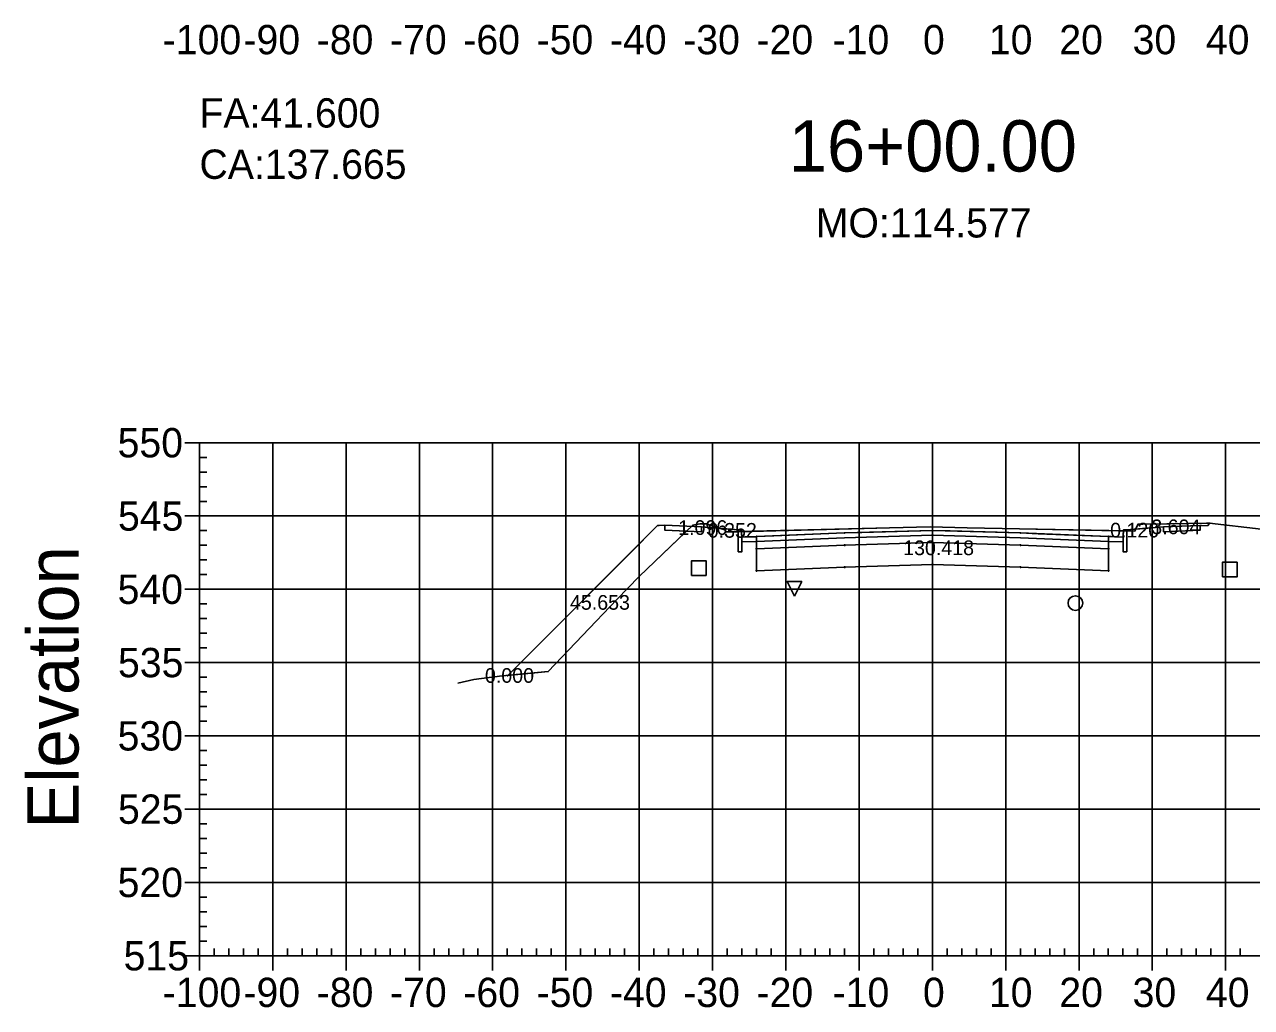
# Model space of a CAD drawing. Extents: x 704834 to 709892, y 372981 to 377533.
# Drawn here: x 704913 to 705080.4, y 373285.8 to 373419.9 of the extents above; entities that cross this region are included whole.
import ezdxf

# ---------------------------------------------------------------- set-up
doc = ezdxf.new("R2010")
doc.units = 0
for name, color, linetype in [('1', 7, 'Continuous'), ('10', 7, 'Continuous'), ('13', 7, 'Continuous'), ('14', 7, 'Continuous'), ('4', 7, 'Continuous'), ('57', 7, 'Continuous'), ('59', 7, 'Continuous'), ('60', 7, 'Continuous'), ('Default_Xsect', 7, 'Continuous'), ('Existing', 7, 'Continuous')]:
    doc.layers.add(name, color=color, linetype=linetype)

msp = doc.modelspace()

# ---------------------------------------------------------------- linework, layer by layer
for points in [[(704999.38, 373351.51), (704978.9, 373331.03)], [(705000.38, 373351.55), (704999.38, 373351.51)], [(705010.38, 373350.95), (705005.38, 373351.35)], [(705063.38, 373350.94), (705068.38, 373351.34)], [(705073.38, 373351.54), (705074.38, 373351.5)], [(705074.38, 373351.5), (705074.7, 373351.82)]]:
    msp.add_lwpolyline(points)
for points in [[(705005.38, 373351.35), (705000.38, 373351.55), (705000.38, 373350.88), (705005.38, 373350.68)], [(705010.88, 373349.95), (705010.79, 373350.95), (705010.38, 373350.95), (705010.38, 373347.95), (705010.88, 373347.95)], [(705036.88, 373350.2), (705048.88, 373349.84), (705060.88, 373349.36), (705060.88, 373350.02), (705048.88, 373350.5), (705036.88, 373350.86), (705024.88, 373350.51), (705012.88, 373350.03), (705012.88, 373349.36), (705024.88, 373349.84)], [(705062.88, 373347.94), (705063.38, 373347.94), (705063.38, 373350.94), (705062.96, 373350.94), (705062.88, 373349.94)], [(705068.38, 373350.67), (705073.38, 373350.87), (705073.38, 373351.54), (705068.38, 373351.34)], [(705012.88, 373350.03), (705010.88, 373349.95), (705010.88, 373349.28), (705012.88, 373349.36)], [(705036.88, 373349.2), (705048.88, 373348.84), (705060.88, 373348.36), (705060.88, 373349.36), (705048.88, 373349.84), (705036.88, 373350.2), (705024.88, 373349.84), (705012.88, 373349.36), (705012.88, 373348.36), (705024.88, 373348.84)], [(705036.88, 373346.2), (705048.88, 373345.84), (705060.88, 373345.36), (705060.88, 373348.36), (705048.88, 373348.84), (705036.88, 373349.2), (705024.88, 373348.84), (705012.88, 373348.36), (705012.88, 373345.36), (705024.88, 373345.84)], [(705024.83, 373348.79), (705024.93, 373348.79), (705024.93, 373348.89), (705024.83, 373348.89)], [(705036.83, 373350.15), (705036.93, 373350.15), (705036.93, 373350.25), (705036.83, 373350.25)], [(705036.83, 373349.15), (705036.93, 373349.15), (705036.93, 373349.25), (705036.83, 373349.25)], [(705048.83, 373348.79), (705048.93, 373348.79), (705048.93, 373348.89), (705048.83, 373348.89)], [(705060.88, 373349.36), (705062.88, 373349.28), (705062.88, 373349.94), (705060.88, 373350.02)], [(705012.83, 373348.31), (705012.93, 373348.31), (705012.93, 373348.41), (705012.83, 373348.41)], [(705060.83, 373348.31), (705060.93, 373348.31), (705060.93, 373348.41), (705060.83, 373348.41)], [(705012.83, 373345.31), (705012.93, 373345.31), (705012.93, 373345.41), (705012.83, 373345.41)], [(705024.83, 373345.79), (705024.93, 373345.79), (705024.93, 373345.89), (705024.83, 373345.89)], [(705036.83, 373346.15), (705036.93, 373346.15), (705036.93, 373346.25), (705036.83, 373346.25)], [(705048.83, 373345.79), (705048.93, 373345.79), (705048.93, 373345.89), (705048.83, 373345.89)], [(705060.83, 373345.31), (705060.93, 373345.31), (705060.93, 373345.41), (705060.83, 373345.41)]]:
    msp.add_lwpolyline(points, close=True)
at = {"layer": '1'}
for points in [[(704978.94, 373331.07), (704984.45, 373331.6), (704993.8, 373341.43), (704996.86, 373344.58), (705003.32, 373350.76), (705000.38, 373350.88), (705000.38, 373351.55), (704999.57, 373351.52), (704999.38, 373351.51)], [(705003.32, 373350.76), (705004.17, 373351.58), (705005.13, 373351.73), (705006, 373351.74), (705007.82, 373351.15), (705006.35, 373351.27), (705005.38, 373351.35), (705005.38, 373350.68)], [(705007.82, 373351.15), (705008.54, 373350.92), (705008.68, 373350.64), (705010.38, 373350.68), (705010.38, 373350.95)], [(705010.38, 373350.68), (705031.01, 373351.2), (705036.55, 373351.34), (705041.59, 373351.22), (705048.77, 373351.08), (705063.38, 373350.79), (705063.38, 373347.94), (705062.88, 373347.94), (705062.88, 373349.28), (705060.88, 373349.36), (705060.88, 373348.36), (705060.88, 373345.36), (705048.88, 373345.84), (705036.88, 373346.2), (705024.88, 373345.84), (705012.88, 373345.36), (705012.88, 373348.36), (705012.88, 373349.36), (705010.88, 373349.28), (705010.88, 373347.95), (705010.38, 373347.95)], [(705063.38, 373350.79), (705064.49, 373350.77), (705064.61, 373351.04), (705064.39, 373351.02), (705063.38, 373350.94)], [(705064.61, 373351.04), (705064.76, 373351.38), (705064.94, 373351.71), (705065.58, 373351.72), (705068.85, 373351.73), (705069.27, 373351.75), (705074.26, 373351.82), (705074.66, 373351.83), (705074.7, 373351.82), (705074.38, 373351.5), (705073.58, 373351.53), (705073.38, 373351.54), (705073.38, 373350.87), (705068.38, 373350.67), (705068.38, 373351.34)], [(705018.05, 373341.87), (705017.05, 373343.87), (705019.05, 373343.87)], [(704978.9, 373331.03), (704978.9, 373331.07), (704978.94, 373331.07)]]:
    msp.add_lwpolyline(points, close=True, dxfattribs=at)
at = {"layer": '10'}
msp.add_lwpolyline([(705004, 373344.71), (705006, 373344.71), (705006, 373346.71), (705004, 373346.71)], close=True, dxfattribs=at)
at = {"layer": '13'}
msp.add_circle((705056.38, 373340.93), 1, dxfattribs=at)
at = {"layer": '14'}
for points in [[(705024.88, 373350.51), (705024.88, 373350.56), (705024.88, 373350.51), (705024.83, 373350.51), (705024.88, 373350.51), (705024.88, 373350.46), (705024.88, 373350.51), (705024.93, 373350.51)], [(705036.88, 373350.86), (705036.88, 373350.91), (705036.88, 373350.86), (705036.83, 373350.86), (705036.88, 373350.86), (705036.88, 373350.81), (705036.88, 373350.86), (705036.93, 373350.86)], [(705048.88, 373350.5), (705048.88, 373350.55), (705048.88, 373350.5), (705048.83, 373350.5), (705048.88, 373350.5), (705048.88, 373350.45), (705048.88, 373350.5), (705048.93, 373350.5)], [(705074.7, 373351.82), (705074.7, 373351.87), (705074.7, 373351.82), (705074.65, 373351.82), (705074.7, 373351.82), (705074.7, 373351.77), (705074.7, 373351.82), (705074.75, 373351.82)], [(705012.88, 373350.03), (705012.88, 373350.08), (705012.88, 373350.03), (705012.83, 373350.03), (705012.88, 373350.03), (705012.88, 373349.98), (705012.88, 373350.03), (705012.93, 373350.03)], [(705060.88, 373350.02), (705060.88, 373350.07), (705060.88, 373350.02), (705060.83, 373350.02), (705060.88, 373350.02), (705060.88, 373349.97), (705060.88, 373350.02), (705060.93, 373350.02)], [(704978.9, 373331.03), (704978.9, 373331.08), (704978.9, 373331.03), (704978.85, 373331.03), (704978.9, 373331.03), (704978.9, 373330.98), (704978.9, 373331.03), (704978.95, 373331.03)]]:
    msp.add_lwpolyline(points, dxfattribs=at)
at = {"layer": '4'}
msp.add_lwpolyline([(705076.43, 373344.51), (705078.43, 373344.51), (705078.43, 373346.51), (705076.43, 373346.51)], close=True, dxfattribs=at)
at = {"layer": '57'}
for p, q in [((704934.87, 373362.82), (704936.87, 373362.82)), ((704936.87, 373362.82), (705136.87, 373362.82)), ((704936.87, 373292.82), (704936.87, 373362.82)), ((704936.87, 373292.82), (704936.87, 373362.82)), ((704946.87, 373292.82), (704946.87, 373362.82)), ((704956.87, 373292.82), (704956.87, 373362.82)), ((704966.87, 373292.82), (704966.87, 373362.82)), ((704976.87, 373292.82), (704976.87, 373362.82)), ((704986.87, 373292.82), (704986.87, 373362.82)), ((704996.87, 373292.82), (704996.87, 373362.82)), ((705006.87, 373292.82), (705006.87, 373362.82)), ((705016.87, 373292.82), (705016.87, 373362.82)), ((705026.87, 373292.82), (705026.87, 373362.82)), ((705036.87, 373292.82), (705036.87, 373362.82)), ((705046.87, 373292.82), (705046.87, 373362.82)), ((705056.87, 373292.82), (705056.87, 373362.82)), ((705066.87, 373292.82), (705066.87, 373362.82)), ((705076.87, 373292.82), (705076.87, 373362.82)), ((704936.87, 373360.82), (704937.87, 373360.82)), ((704936.87, 373358.82), (704937.87, 373358.82)), ((704936.87, 373356.82), (704937.87, 373356.82)), ((704936.87, 373354.82), (704937.87, 373354.82)), ((704934.87, 373352.82), (704936.87, 373352.82)), ((704936.87, 373352.82), (705136.87, 373352.82)), ((704936.87, 373350.82), (704937.87, 373350.82)), ((704936.87, 373348.82), (704937.87, 373348.82)), ((704936.87, 373346.82), (704937.87, 373346.82)), ((704936.87, 373344.82), (704937.87, 373344.82)), ((704934.87, 373342.82), (704936.87, 373342.82)), ((704936.87, 373342.82), (705136.87, 373342.82)), ((704936.87, 373340.82), (704937.87, 373340.82)), ((704936.87, 373338.82), (704937.87, 373338.82)), ((704936.87, 373336.82), (704937.87, 373336.82)), ((704936.87, 373334.82), (704937.87, 373334.82)), ((704934.87, 373332.82), (704936.87, 373332.82)), ((704936.87, 373332.82), (705136.87, 373332.82)), ((704936.87, 373330.82), (704937.87, 373330.82)), ((704936.87, 373328.82), (704937.87, 373328.82)), ((704936.87, 373326.82), (704937.87, 373326.82)), ((704936.87, 373324.82), (704937.87, 373324.82)), ((704934.87, 373322.82), (704936.87, 373322.82)), ((704936.87, 373322.82), (705136.87, 373322.82)), ((704936.87, 373320.82), (704937.87, 373320.82)), ((704936.87, 373318.82), (704937.87, 373318.82)), ((704936.87, 373316.82), (704937.87, 373316.82)), ((704936.87, 373314.82), (704937.87, 373314.82)), ((704934.87, 373312.82), (704936.87, 373312.82)), ((704936.87, 373312.82), (705136.87, 373312.82)), ((704936.87, 373310.82), (704937.87, 373310.82)), ((704936.87, 373308.82), (704937.87, 373308.82)), ((704936.87, 373306.82), (704937.87, 373306.82)), ((704936.87, 373304.82), (704937.87, 373304.82)), ((704934.87, 373302.82), (704936.87, 373302.82)), ((704936.87, 373302.82), (705136.87, 373302.82)), ((704936.87, 373300.82), (704937.87, 373300.82)), ((704936.87, 373298.82), (704937.87, 373298.82)), ((704936.87, 373296.82), (704937.87, 373296.82)), ((704936.87, 373294.82), (704937.87, 373294.82)), ((704938.87, 373292.82), (704938.87, 373293.82)), ((704940.87, 373292.82), (704940.87, 373293.82)), ((704942.87, 373292.82), (704942.87, 373293.82)), ((704944.87, 373292.82), (704944.87, 373293.82)), ((704948.87, 373292.82), (704948.87, 373293.82)), ((704950.87, 373292.82), (704950.87, 373293.82)), ((704952.87, 373292.82), (704952.87, 373293.82)), ((704954.87, 373292.82), (704954.87, 373293.82)), ((704958.87, 373292.82), (704958.87, 373293.82)), ((704960.87, 373292.82), (704960.87, 373293.82)), ((704962.87, 373292.82), (704962.87, 373293.82)), ((704964.87, 373292.82), (704964.87, 373293.82)), ((704968.87, 373292.82), (704968.87, 373293.82)), ((704970.87, 373292.82), (704970.87, 373293.82)), ((704972.87, 373292.82), (704972.87, 373293.82)), ((704974.87, 373292.82), (704974.87, 373293.82)), ((704978.87, 373292.82), (704978.87, 373293.82)), ((704980.87, 373292.82), (704980.87, 373293.82)), ((704982.87, 373292.82), (704982.87, 373293.82)), ((704984.87, 373292.82), (704984.87, 373293.82)), ((704988.87, 373292.82), (704988.87, 373293.82)), ((704990.87, 373292.82), (704990.87, 373293.82)), ((704992.87, 373292.82), (704992.87, 373293.82)), ((704994.87, 373292.82), (704994.87, 373293.82)), ((704998.87, 373292.82), (704998.87, 373293.82)), ((705000.87, 373292.82), (705000.87, 373293.82)), ((705002.87, 373292.82), (705002.87, 373293.82)), ((705004.87, 373292.82), (705004.87, 373293.82)), ((705008.87, 373292.82), (705008.87, 373293.82)), ((705010.87, 373292.82), (705010.87, 373293.82)), ((705012.87, 373292.82), (705012.87, 373293.82)), ((705014.87, 373292.82), (705014.87, 373293.82)), ((705018.87, 373292.82), (705018.87, 373293.82)), ((705020.87, 373292.82), (705020.87, 373293.82)), ((705022.87, 373292.82), (705022.87, 373293.82)), ((705024.87, 373292.82), (705024.87, 373293.82)), ((705028.87, 373292.82), (705028.87, 373293.82)), ((705030.87, 373292.82), (705030.87, 373293.82)), ((705032.87, 373292.82), (705032.87, 373293.82)), ((705034.87, 373292.82), (705034.87, 373293.82)), ((705038.87, 373292.82), (705038.87, 373293.82)), ((705040.87, 373292.82), (705040.87, 373293.82)), ((705042.87, 373292.82), (705042.87, 373293.82)), ((705044.87, 373292.82), (705044.87, 373293.82)), ((705048.87, 373292.82), (705048.87, 373293.82)), ((705050.87, 373292.82), (705050.87, 373293.82)), ((705052.87, 373292.82), (705052.87, 373293.82)), ((705054.87, 373292.82), (705054.87, 373293.82)), ((705058.87, 373292.82), (705058.87, 373293.82)), ((705060.87, 373292.82), (705060.87, 373293.82)), ((705062.87, 373292.82), (705062.87, 373293.82)), ((705064.87, 373292.82), (705064.87, 373293.82)), ((705068.87, 373292.82), (705068.87, 373293.82)), ((705070.87, 373292.82), (705070.87, 373293.82)), ((705072.87, 373292.82), (705072.87, 373293.82)), ((705074.87, 373292.82), (705074.87, 373293.82)), ((705078.87, 373292.82), (705078.87, 373293.82)), ((704934.87, 373292.82), (704936.87, 373292.82)), ((704936.87, 373292.82), (705136.87, 373292.82)), ((704936.87, 373292.82), (705136.87, 373292.82)), ((704936.87, 373290.82), (704936.87, 373292.82)), ((704946.87, 373290.82), (704946.87, 373292.82)), ((704956.87, 373290.82), (704956.87, 373292.82)), ((704966.87, 373290.82), (704966.87, 373292.82)), ((704976.87, 373290.82), (704976.87, 373292.82)), ((704986.87, 373290.82), (704986.87, 373292.82)), ((704996.87, 373290.82), (704996.87, 373292.82)), ((705006.87, 373290.82), (705006.87, 373292.82)), ((705016.87, 373290.82), (705016.87, 373292.82)), ((705026.87, 373290.82), (705026.87, 373292.82)), ((705036.87, 373290.82), (705036.87, 373292.82)), ((705046.87, 373290.82), (705046.87, 373292.82)), ((705056.87, 373290.82), (705056.87, 373292.82)), ((705066.87, 373290.82), (705066.87, 373292.82)), ((705076.87, 373290.82), (705076.87, 373292.82))]:
    msp.add_line(p, q, dxfattribs=at)
at = {"layer": 'Default_Xsect'}
msp.add_lwpolyline([(704978.9, 373331.03), (704995.57, 373347.7), (704999.38, 373351.51), (704999.57, 373351.52), (705000.38, 373351.55), (705001.34, 373351.51), (705005.38, 373351.35), (705006.35, 373351.27), (705010.38, 373350.95), (705010.46, 373350.95), (705010.79, 373350.95), (705010.81, 373350.75), (705010.88, 373349.95), (705011.27, 373349.96), (705012.88, 373350.03), (705015.24, 373350.12), (705024.88, 373350.51), (705027.26, 373350.58), (705036.88, 373350.86), (705039.28, 373350.79), (705048.88, 373350.5), (705051.3, 373350.4), (705060.88, 373350.02), (705061.28, 373350.01), (705062.88, 373349.94), (705062.89, 373350.14), (705062.96, 373350.94), (705063.04, 373350.94), (705063.38, 373350.94), (705064.39, 373351.02), (705068.38, 373351.34), (705069.4, 373351.38), (705073.38, 373351.54), (705073.58, 373351.53), (705074.38, 373351.5), (705074.62, 373351.75), (705074.7, 373351.82)], dxfattribs=at)
at = {"layer": 'Existing'}
msp.add_lwpolyline([(704972.11, 373330.02), (704974.32, 373330.53), (704978.19, 373331), (704984.45, 373331.6), (704993.8, 373341.43), (704996.86, 373344.58), (705004.17, 373351.58), (705005.13, 373351.73), (705006, 373351.74), (705008.54, 373350.92), (705008.68, 373350.64), (705031.01, 373351.2), (705036.55, 373351.34), (705041.59, 373351.22), (705048.77, 373351.08), (705064.49, 373350.77), (705064.76, 373351.38), (705064.94, 373351.71), (705065.58, 373351.72), (705068.85, 373351.73), (705069.27, 373351.75), (705074.26, 373351.82), (705074.66, 373351.83), (705081.74, 373351.01)], dxfattribs=at)

# ---------------------------------------------------------------- texts
msp.add_text('CA:137.665', height=4).set_placement((704936.87, 373398.82))
at = {"layer": '1'}
msp.add_text('16+00.00', height=7, dxfattribs=at).set_placement((705017.28, 373399.82))
at = {"layer": '14'}
for p in [(705000.34, 373351.5), (705000.34, 373350.83), (705005.34, 373350.63), (705068.34, 373350.62), (705073.34, 373351.49), (705073.34, 373350.82)]:
    msp.add_text('+', height=0.1, dxfattribs=at).set_placement(p)
at = {"layer": '57'}
for s, p in [('-100', (704931.86, 373415.82)), ('-90', (704942.87, 373415.82)), ('-80', (704952.87, 373415.82)), ('-70', (704962.87, 373415.82)), ('-60', (704972.87, 373415.82)), ('-50', (704982.87, 373415.82)), ('-40', (704992.87, 373415.82)), ('-30', (705002.87, 373415.82)), ('-20', (705012.87, 373415.82)), ('-10', (705023.26, 373415.82)), ('0', (705035.58, 373415.82)), ('10', (705044.57, 373415.82)), ('20', (705054.18, 373415.82)), ('30', (705064.18, 373415.82)), ('40', (705074.18, 373415.82)), ('550', (704925.7, 373360.82)), ('545', (704925.75, 373350.82)), ('540', (704925.7, 373340.82)), ('535', (704925.75, 373330.82)), ('530', (704925.7, 373320.82)), ('525', (704925.75, 373310.82)), ('520', (704925.7, 373300.82)), ('515', (704926.52, 373290.82)), ('-100', (704931.86, 373285.82)), ('-90', (704942.87, 373285.82)), ('-80', (704952.87, 373285.82)), ('-70', (704962.87, 373285.82)), ('-60', (704972.87, 373285.82)), ('-50', (704982.87, 373285.82)), ('-40', (704992.87, 373285.82)), ('-30', (705002.87, 373285.82)), ('-20', (705012.87, 373285.82)), ('-10', (705023.26, 373285.82)), ('0', (705035.58, 373285.82)), ('10', (705044.57, 373285.82)), ('20', (705054.18, 373285.82)), ('30', (705064.18, 373285.82)), ('40', (705074.18, 373285.82))]:
    msp.add_text(s, height=4, dxfattribs=at).set_placement(p)
at = {"layer": '59'}
for s, height, p in [('FA:41.600', 4, (704936.87, 373405.82)), ('MO:114.577', 4, (705020.95, 373390.82)), ('1.096', 2, (705002.19, 373350.24)), ('3.604', 2, (705066.73, 373350.34)), ('0.352', 2, (705006.22, 373349.86)), ('0.120', 2, (705061.12, 373349.89)), ('130.418', 2, (705032.88, 373347.48)), ('45.653', 2, (704987.42, 373340.03)), ('0.000', 2, (704975.82, 373330.06))]:
    msp.add_text(s, height=height, dxfattribs=at).set_placement(p)
at = {"layer": '60'}
msp.add_text('Elevation', height=7, rotation=90, dxfattribs=at).set_placement((704920.37, 373310.18))

doc.saveas('drawing.dxf')
